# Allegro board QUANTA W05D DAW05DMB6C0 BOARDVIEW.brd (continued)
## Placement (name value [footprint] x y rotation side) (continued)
R15  1k_2  [RC0201_S]  221.12 115.07 180 bottom
R16  10k/f_2  [RC0201_S]  222.67 115.04 180 bottom
R17  0_6  [RC0603]  224.71 114.25 0 bottom
R18  2.2k_2  [RC0201_S]  238.5 114.03 0 bottom
R19  2.2k/f_2  [RC0201_S]  234.41 113.06 180 bottom
R20  20k/f_4  [RC0402]  251.1 112.45 0 bottom
R21  4.7k_2  [RC0201_S]  234.41 112.4 0 bottom
R22  20k/f_2  [RC0201_S]  218.81 111.99 90 bottom
R23  20k/f_2  [RC0201_S]  218.05 111.99 90 bottom
R24  10k_2  [RC0201_S]  202.3 111.66 90 bottom
R25  4.7k_2  [RC0201_S]  201.67 111.66 90 bottom
R26  *100k/f_4  [RC0402]  210.28 111.56 180 bottom
R27  47k/f_4  [RC0402]  204.59 111.1 270 bottom
R28  *0_4/s  [SHORT0402]  203.32 111.1 270 bottom
R29  12.1k/f_4  [RC0402]  216.81 111 270 bottom
R30  15k  [RC0402]  233.7 110.7 180 bottom
R31  *0_6  [RC0603]  219.07 109.76 180 bottom
R32  1k_2  [RC0201_S]  197.86 109.71 0 bottom
R33  47k/f_4  [RC0402]  211.96 109.63 0 bottom
R34  1.3k/f_4  [RC0402]  235.45 109.45 90 bottom
R35  10k_2  [RC0201_S]  217.16 109.05 270 bottom
R36  100/f_2  [RC0201_S]  215.89 109.05 90 bottom
R37  10k/f_2  [RC0201_S]  210.23 108.79 90 bottom
R38  4.7k/f_2  [RC0201_S]  214.01 108.69 90 bottom
R39  0_2  [RC0201_S]  213.4 108.69 90 bottom
R40  *0_2  [RC0201_S]  197.35 108.95 0 bottom
R41  *0_6  [RC0603]  260.32 108.56 180 bottom
R42  10k_2  [RC0201_S]  262.17 108.54 180 bottom
R43  200k_4  [RC0402]  257.19 108.51 180 bottom
R44  10k_2  [RC0201_S]  255.77 108.51 270 bottom
R45  *4.7k_2  [RC0201_S]  216.07 108.21 0 bottom
R46  4.7k_2  [RC0201_S]  197.35 108.18 0 bottom
R47  2.2k_2  [RC0201_S]  236.29 107.24 270 bottom
R48  4.7k_2  [RC0201_S]  263.36 107.19 180 bottom
R49  *0_2/s  [SHORT0201]  197.22 107.29 180 bottom
R50  10k/f_2  [RC0201_S]  197.48 106.41 0 bottom
R51  *0_8  [RC0805]  253.66 106.15 0 bottom
R52  0_2  [RC0201_S]  263.36 106.1 180 bottom
R53  4.7k_2  [RC0201_S]  197.48 105.64 0 bottom
R54  *0_2  [RC0201_S]  263.36 105.24 0 bottom
R55  130/f_4  [RC0402]  61.84 104.78 90 bottom
R56  10k/f_2  [RC0201_S]  252.26 104.63 0 bottom
R57  10k_2  [RC0201_S]  263.36 104.22 180 bottom
R58  *10k/f_2  [RC0201_S]  252.26 103.92 180 bottom
R59  0_6  [RC0603]  253.89 103.74 90 bottom
R60  10k/f_2  [RC0201_S]  251.07 103.74 0 bottom
R61  16.5k/f_4  [RC0402]  122.29 103.74 0 bottom
R62  3.3k/f_4  [RC0402]  124.33 103.48 0 bottom
R63  0_2  [RC0201_S]  196.08 103.1 270 bottom
R64  0_2  [RC0201_S]  195.06 103.1 270 bottom
R65  10k/f_2  [RC0201_S]  252.6 102.9 180 bottom
R66  *10k/f_2  [RC0201_S]  251.07 102.9 0 bottom
R67  *0_2  [RC0201_S]  259.71 102.47 180 bottom
R68  *0_4  [RC0402]  17.92 104.42 270 bottom
R69  0_4  [RC0402]  81.02 64.24 270 bottom
R70  *0_2  [RC0201_S]  259.71 101.71 0 bottom
R71  100k_4 ntc  [RC0402]  16.6 104.42 90 bottom
R72  100k_4 ntc  [RC0402]  81.02 60.94 270 bottom
R73  *100k/f_2  [RC0201_S]  260.19 100.44 0 bottom
R74  *0_6/s  [SHORT0603]  51.38 99.98 270 bottom
R75  *0_6/s  [SHORT0603]  43.43 99.93 270 bottom
R76  10k/f_2  [RC0201_S]  242.82 99.14 270 bottom
R77  *10k/f_2  [RC0201_S]  242.16 99.14 90 bottom
R78  10k/f_2  [RC0201_S]  240.73 99.04 270 bottom
R79  *10k/f_2  [RC0201_S]  240.07 99.04 90 bottom
R80  *10k/f_2  [RC0201_S]  239.01 99.04 270 bottom
R81  *100k_2  [RC0201_S]  75.07 98.71 270 bottom
R82  *10k/f_2  [RC0201_S]  74.41 98.71 270 bottom
R83  43_4  [RC0402]  198.62 98.61 90 bottom
R84  10k/f_2  [RC0201_S]  201.67 98.56 180 bottom
R85  *100k_2  [RC0201_S]  75.71 98.46 270 bottom
R86  10k/f_2  [RC0201_S]  239.84 98.15 180 bottom
R87  15/f_2  [RC0201_S]  88.66 98.13 180 bottom
R88  10k/f_2  [RC0201_S]  242.18 98.02 270 bottom
R89  *10k/f_2  [RC0201_S]  241.42 98.02 270 bottom
R90  100k_2  [RC0201_S]  69.72 98.01 270 bottom
R91  100k/f_2  [RC0201_S]  15.33 97.82 270 bottom
R92  *10k/f_2  [RC0201_S]  201.67 97.8 180 bottom
R93  *0_4/s  [SHORT0402]  73.53 97.64 180 bottom
R94  *0_4/s  [SHORT0402]  71.37 97.64 180 bottom
R95  *0_2  [RC0201_S]  252.21 97.62 180 bottom
R96  150/f_4  [RC0402]  21.46 97.52 0 bottom
R97  *10k_2  [RC0201_S]  23.87 97.26 0 bottom
R98  *0_2  [RC0201_S]  252.21 96.98 0 bottom
R99  *0_2  [RC0201_S]  245.1 96.75 180 bottom
R100  100k_2  [RC0201_S]  195.24 96.6 180 bottom
R101  *6.2k/f_4  [RC0402]  243.32 96.53 0 bottom
R102  10k_2  [RC0201_S]  193.62 96.45 90 bottom
R103  10k_2  [RC0201_S]  192.91 96.45 90 bottom
R104  10k_2  [RC0201_S]  194.4 96.37 90 bottom
R105  *0_2  [RC0201_S]  252.21 96.35 0 bottom
R106  *0_2  [RC0201_S]  245.1 95.99 180 bottom
R107  4.7k_2  [RC0201_S]  223.08 95.86 0 bottom
R108  *10_4  [RC0402]  199.59 95.84 90 bottom
R109  *0_2  [RC0201_S]  252.21 95.71 180 bottom
R110  *0_4  [RC0402]  263.06 95.36 270 bottom
R111  *0_2  [RC0201_S]  245.1 95.23 0 bottom
R112  3.3k/f_2  [RC0402]  76.55 95.2 270 bottom
R113  10k_2  [RC0201_S]  95.12 95.13 180 bottom
R114  10k_2  [RC0201_S]  20.57 95.1 180 bottom
R115  *0_2  [RC0201_S]  252.21 95.08 180 bottom
R116  4.7k_2  [RC0201_S]  201.62 95 180 bottom
R117  *121/f_4  [RC0402]  254.63 94.98 180 bottom
R118  *0_8  [RC0805]  23.36 94.98 90 bottom
R119  *0_2  [RC0201_S]  252.21 94.44 0 bottom
R120  10k/f_2  [RC0201_S]  260.98 94.21 180 bottom
R121  *0_4/s  [SHORT0402]  20.82 94.21 180 bottom
R122  *4.99k/f_2  [RC0201_S]  237.23 93.99 0 bottom
R123  *0_2  [RC0201_S]  236.21 93.99 180 bottom
R124  *0_2  [RC0201_S]  262.12 93.96 180 bottom
R125  4.7k_2  [RC0201_S]  223.08 93.96 0 bottom
R126  *0_2  [RC0201_S]  245.79 93.93 90 bottom
R127  100k/f_2  [RC0201_S]  14.57 93.88 90 bottom
R128  1k_2  [RC0201_S]  13.94 93.88 90 bottom
R129  1k/f_2  [RC0201_S]  13.28 93.88 90 bottom
R130  *4.99k/f_2  [RC0201_S]  226.84 93.81 180 bottom
R131  15/f_2  [RC0201_S]  76.57 93.81 0 bottom
R132  4.7k_2  [RC0201_S]  224.63 93.32 0 bottom
R133  *4.99k/f_2  [RC0201_S]  237.23 93.22 0 bottom
R134  *4.99k/f_2  [RC0201_S]  236.21 93.22 0 bottom
R135  0_2  [RC0201_S]  259.55 93.2 90 bottom
R136  0_2  [RC0201_S]  258.79 93.2 90 bottom
R137  *0_2  [RC0201_S]  228.47 93.15 180 bottom
R138  *4.99k/f_2  [RC0201_S]  226.84 93.15 180 bottom
R139  *10k/f_2  [RC0201_S]  246.52 92.82 270 bottom
R140  *0_6/s  [SHORT0603]  82.08 92.72 180 bottom
R141  15/f_2  [RC0201_S]  87.62 92.56 270 bottom
R142  *0_4  [RC0402]  201.57 92.54 90 bottom
R143  0_4  [RC0402]  12.92 92.51 180 bottom
R144  15/f_2  [RC0201_S]  197.2 92.44 90 bottom
R145  15/f_2  [RC0201_S]  196.33 92.44 90 bottom
R146  *4.99k/f_2  [RC0201_S]  228.47 92.41 180 bottom
R147  *4.99k/f_2  [RC0201_S]  226.84 92.41 180 bottom
R148  *1k_2  [RC0201_S]  64.41 92.41 180 bottom
R149  *4.99k/f_2  [RC0201_S]  237.23 92.33 0 bottom
R150  *4.99k/f_2  [RC0201_S]  236.21 92.33 0 bottom
R151  4.7k_2  [RC0201_S]  224.63 92.33 0 bottom
R152  0_2  [RC0201_S]  262.5 92.31 270 bottom
R153  3.3k/f_2  [RC0402]  86.53 92.28 90 bottom
R154  1m_2  [RC0201_S]  48.79 92.18 0 bottom
R155  *0_6/s  [SHORT0603]  61 92.03 90 bottom
R156  *121/f_4  [RC0402]  256.41 91.8 180 bottom
R157  *121/f_4  [RC0402]  254.37 91.8 180 bottom
R158  *121/f_4  [RC0402]  251.96 91.8 180 bottom
R159  15/f_2  [RC0201_S]  76.19 91.8 0 bottom
R160  *1k_2  [RC0201_S]  64.41 91.78 180 bottom
R161  *4.7k/f_2  [RC0201_S]  224.63 91.7 0 bottom
R162  10k/f_2  [RC0201_S]  223.08 91.7 0 bottom
R163  *4.99k/f_2  [RC0201_S]  226.84 91.55 180 bottom
R164  *0_4/s  [SHORT0402]  46.73 91.55 270 bottom
R165  *4.99k/f_2  [RC0201_S]  237.23 91.52 0 bottom
R166  *0_2  [RC0201_S]  236.21 91.52 0 bottom
R167  *4.99k/f_2  [RC0201_S]  228.47 91.52 0 bottom
R168  *0_4  [RC0402]  39.36 91.47 270 bottom
R169  3.01k/f_2  [RC0201_S]  62.1 91.42 0 bottom
R170  10k/f_2  [RC0201_S]  43.17 91.17 270 bottom
R171  10k_2  [RC0201_S]  42.54 91.17 270 bottom
R172  8.2k/f_4  [RC0402]  55.59 91.12 0 bottom
R173  15/f_2  [RC0201_S]  76.7 91.04 0 bottom
R174  3.01k/f_2  [RC0201_S]  48 91.04 270 bottom
R175  10k_2  [RC0201_S]  20.44 91.04 180 bottom
R176  10k/f_2  [RC0201_S]  224.63 90.86 180 bottom
R177  10k_2  [RC0201_S]  63.44 90.81 180 bottom
R178  4.7k_2  [RC0201_S]  223.08 90.78 0 bottom
R179  *0_6  [RC0603]  82.54 90.78 270 bottom
R180  3.01k/f_2  [RC0201_S]  50.77 90.78 0 bottom
R181  24.9/f_2  [RC0201_S]  49.65 90.78 180 bottom
R182  *4.99k/f_2  [RC0201_S]  228.47 90.56 0 bottom
R183  *4.99k/f_2  [RC0201_S]  226.84 90.56 0 bottom
R184  2.2k_2  [RC0201_S]  195.32 90.4 90 bottom
R185  2.2k_2  [RC0201_S]  194.68 90.4 90 bottom
R186  4.7k_2  [RC0201_S]  223.08 90.12 0 bottom
R187  *0_4  [RC0402]  69.13 89.77 180 bottom
R188  10k_2  [RC0201_S]  79.6 89.69 270 bottom
R189  10k_2  [RC0201_S]  78.96 89.69 270 bottom
R190  10k_2  [RC0201_S]  78.33 89.69 270 bottom
R191  10k_2  [RC0201_S]  77.69 89.69 270 bottom
R192  *4.99k/f_2  [RC0201_S]  226.84 89.64 180 bottom
R193  *4.7k_2  [RC0201_S]  100.7 89.64 90 bottom
R194  *4.7k_2  [RC0201_S]  100.07 89.64 270 bottom
R195  *0_2  [RC0201_S]  99.43 89.64 270 bottom
R196  0_4  [RC0402]  17.01 89.64 0 bottom
R197  1m_4  [RC0402]  189.22 89.51 0 bottom
R198  10k_2  [RC0201_S]  76.95 89.51 270 bottom
R199  10k_2  [RC0201_S]  76.32 89.51 270 bottom
R200  10k/f_2  [RC0201_S]  20.06 89.51 0 bottom
R201  *10k_2  [RC0201_S]  199.31 89.26 180 bottom
R202  10k_2  [RC0201_S]  71.7 88.93 270 bottom
R203  10k_2  [RC0201_S]  71.09 88.91 270 bottom
R204  10k_2  [RC0201_S]  70.48 88.91 270 bottom
R205  *0_4/s  [SHORT0402]  69.08 88.75 0 bottom
R206  *0_4/s  [SHORT0402]  219.45 88.63 180 bottom
R207  *0_4  [RC0402]  217.16 88.65 0 bottom
R208  10k_2  [RC0201_S]  72.33 88.6 270 bottom
R209  *4.7k/f_2  [RC0201_S]  188.66 88.58 180 bottom
R210  15/f_2  [RC0201_S]  231.31 88.55 180 bottom
R211  0_4  [RC0402]  196.21 88.5 90 bottom
R212  *0_4  [RC0402]  195.19 88.5 90 bottom
R213  *0_4/s  [SHORT0402]  20.06 88.5 180 bottom
R214  10k_2  [RC0201_S]  72.99 88.17 270 bottom
R215  10k_2  [RC0201_S]  76.07 88.12 0 bottom
R216  10k_2  [RC0201_S]  75.18 88.12 270 bottom
R217  10k_2  [RC0201_S]  74.54 88.12 270 bottom
R218  10k_2  [RC0201_S]  66.74 88.12 270 bottom
R219  10k_2  [RC0201_S]  66.11 88.12 270 bottom
R220  100k_2  [RC0201_S]  191.64 87.86 90 bottom
R221  100k/f_2  [RC0201_S]  229.76 87.69 180 bottom
R222  4.7k_2  [RC0201_S]  214.47 87.61 270 bottom
R223  4.7k_2  [RC0201_S]  220.57 90.66 270 bottom
R224  4.7k_2  [RC0201_S]  213.12 87.61 270 bottom
R225  4.7k_2  [RC0201_S]  212.49 87.61 270 bottom
R226  4.7k_2  [RC0201_S]  206.34 87.61 0 bottom
R227  *100k_4  [RC0402]  204.46 87.61 90 bottom
R228  *0_4  [RC0402]  202.43 87.48 270 bottom
R229  15/f_2  [RC0201_S]  232.68 87.31 0 bottom
R230  *0_4/s  [SHORT0402]  77.08 87.23 0 bottom
R231  3.3/f_4  [RC0402]  220.21 86.97 270 bottom
R232  3.3/f_4  [RC0402]  219.07 86.97 270 bottom
R233  3.3/f_4  [RC0402]  217.8 86.97 270 bottom
R234  3.3/f_4  [RC0402]  216.65 86.97 270 bottom
R235  *0_4  [RC0402]  91.81 86.95 180 bottom
R236  *0_2/s  [SHORT0201]  199.64 87.1 90 bottom
R237  10k/f_2  [RC0201_S]  224.4 86.85 90 bottom
R238  15/f_2  [RC0201_S]  82.19 87.46 90 bottom
R239  *0_2  [CC0201_S]  71.8 86.82 0 bottom
R240  1k_2  [RC0201_S]  15.74 86.75 90 bottom
R241  *0_4  [RC0402]  93.51 86.44 90 bottom
R242  10k_2  [RC0201_S]  77.41 86.31 0 bottom
R243  100/f_2  [RC0201_S]  20.06 86.06 0 bottom
R244  *51_2  [RC0201_S]  17.65 85.96 180 bottom
R245  *10k_2  [RC0201_S]  224.12 85.93 0 bottom
R246  0_8/fm  [RC0603]  222.17 85.83 0 bottom
R247  *0_4/s  [SHORT0402]  74.29 85.7 270 bottom
R248  1k_2  [RC0201_S]  14.65 85.48 180 bottom
R249  1k/f_2  [RC0201_S]  13.58 85.48 0 bottom
R250  100k/f_2  [RC0201_S]  12.51 85.48 0 bottom
R251  100/f_2  [RC0201_S]  20.06 85.43 0 bottom
R252  10k_4  [RC0402]  213.99 85.32 0 bottom
R253  *51_2  [RC0201_S]  17.65 85.2 180 bottom
R254  100k_2  [RC0201_S]  75.3 85.04 270 bottom
R255  *100k_2  [RC0201_S]  72.38 85.07 270 bottom
R256  *0_4/s  [SHORT0402]  11.17 85.07 90 bottom
R257  2.2k_2  [RC0201_S]  180.89 84.38 180 bottom
R258  51_2  [RC0201_S]  17.65 84.43 180 bottom
R259  0_6  [RC0603]  232.88 82.68 0 bottom
R260  *2.2k_2  [RC0201_S]  227.96 83.8 0 bottom
R261  56.2/f_2  [RC0201_S]  20.03 83.27 180 bottom
R262  100k/f_2  [RC0201_S]  11.57 83.16 270 bottom
R263  100/f_4  [RC0402]  221.99 83.04 0 bottom
R264  2.2k_2  [RC0201_S]  80.87 82.91 270 bottom
R265  *0_4/s  [SHORT0402]  20.06 82.4 180 bottom
R266  62_4  [RC0402]  18.46 82.3 90 bottom
R267  0_2  [RC0201_S]  222.12 82.15 180 bottom
R268  2.2k_2  [RC0201_S]  80.87 81.34 90 bottom
R269  *0_6  [RC0603]  11.3 81.29 90 bottom
R270  51_2  [RC0201_S]  14.72 81.13 180 bottom
R271  *0_6  [RC0603]  73.27 80.75 0 bottom
R272  0_2  [CC0201_S]  70.27 80.57 0 bottom
R273  10k_2  [RC0201_S]  68.7 80.57 180 bottom
R274  *0_2  [RC0201_S]  66.06 80.57 90 bottom
R275  0_2  [RC0201_S]  221.61 80.5 180 bottom
R276  43_4  [RC0402]  20.06 80.24 0 bottom
R277  75/f_4  [RC0402]  17.9 80.24 180 bottom
R278  0_2  [CC0201_S]  15.92 80.17 0 bottom
R279  30.1_4  [RC0402]  201.67 79.99 180 bottom
R280  *0_2  [RC0201_S]  104.13 79.99 90 bottom
R281  *0_2  [RC0201_S]  102.23 79.99 90 bottom
R282  *0_2  [RC0201_S]  99.43 79.99 90 bottom
R283  *0_2  [RC0201_S]  98.8 79.99 90 bottom
R284  *0_2  [RC0201_S]  96.89 79.99 90 bottom
R285  10k_2  [RC0201_S]  68.7 79.96 180 bottom
R286  *4.7k/f_4  [RC0402]  95.24 79.86 180 bottom
R287  10k_2  [RC0201_S]  67.68 79.86 0 bottom
R288  10k_2  [RC0201_S]  66.11 79.76 180 bottom
R289  33_2  [RC0201_S]  221.73 79.23 0 bottom
R290  8.2k/f_4  [RC0402]  69.84 79.23 270 bottom
R291  10k_2  [RC0201_S]  68.7 79.2 180 bottom
R292  *0_2  [RC0201_S]  201.29 79.1 180 bottom
R293  10k_2  [RC0201_S]  67.68 79.1 0 bottom
R294  10k_2  [RC0201_S]  66.11 79 180 bottom
R295  *0_2  [CC0201_S]  15.11 78.95 180 bottom
R296  *0_2  [RC0201_S]  201.29 78.47 180 bottom
R297  *33_4  [RC0402]  101.34 78.47 0 bottom
R298  *22_4  [RC0402]  99.31 78.47 180 bottom
R299  4.7k_2  [RC0201_S]  79.24 78.47 270 bottom
R300  2.2k_2  [RC0201_S]  76.17 78.39 270 bottom
R301  0_2  [CC0201_S]  15.11 78.31 180 bottom
R302  10k_2  [RC0201_S]  67.63 78.21 180 bottom
R303  *10k_2  [RC0201_S]  68.57 77.45 270 bottom
R304  10k_2  [RC0201_S]  66.11 78.21 180 bottom
R305  *1k_2  [RC0201_S]  69.21 77.45 90 bottom
R306  49.9/f_4  [RC0402]  20.82 77.45 90 bottom
R307  1k_2  [RC0201_S]  12.95 77.45 90 bottom
R308  1k_2  [RC0201_S]  12.31 77.45 270 bottom
R309  *0_4/s  [SHORT0402]  70.6 77.07 180 bottom
R310  *0_2  [RC0201_S]  225.42 77.07 90 bottom
R311  *0_4/s  [SHORT0402]  72.76 76.94 0 bottom
R312  4.7k_2  [RC0201_S]  79.24 76.92 90 bottom
R313  10k_2  [RC0201_S]  66.11 76.84 180 bottom
R314  10k_2  [RC0201_S]  67.63 76.81 0 bottom
R315  2.2k_2  [RC0201_S]  76.17 76.59 90 bottom
R316  30.1_4  [RC0402]  201.67 76.43 180 bottom
R317  10k_2  [RC0201_S]  220.46 76.18 180 bottom
R318  *2k/f_4  [RC0402]  206.49 76.05 180 bottom
R319  *2k/f_4  [RC0402]  204.46 76.05 0 bottom
R320  10k_2  [RC0201_S]  70.58 76.05 0 bottom
R321  *10k_2  [RC0201_S]  67.99 75.98 180 bottom
R322  2.2k_2  [RC0201_S]  215.77 75.93 90 bottom
R323  *1k_2  [RC0201_S]  20.19 75.93 0 bottom
R324  100k_2  [RC0201_S]  69.13 75.7 180 bottom
R325  10k_2  [RC0201_S]  71.9 75.39 180 bottom
R326  *1k_2  [RC0201_S]  13.02 75.32 270 bottom
R327  39.2k/f_4  [RC0402]  218.03 75.29 90 bottom
R328  0_8  [RC0805]  17.44 75.21 180 bottom
R329  51_2  [RC0201_S]  20.19 75.16 180 bottom
R330  *0_2  [RC0201_S]  203.4 75.14 180 bottom
R331  *0_2/s  [SHORT0201]  205.48 74.78 270 bottom
R332  *0_2/s  [SHORT0201]  204.46 74.78 270 bottom
R333  10k_2  [RC0201_S]  66.08 74.91 180 bottom
R334  2.49k/f_4  [RC0402]  210.81 75.16 270 bottom
R335  4.7k_4  [RC0402]  207.1 74.68 180 bottom
R336  *10k_2  [RC0201_S]  70.76 74.66 180 bottom
R337  10k_2  [RC0201_S]  69.18 74.55 0 bottom
R338  10k_2  [RC0201_S]  67.58 74.55 180 bottom
R339  100k/f_2  [RC0201_S]  220.46 74.53 0 bottom
R340  10k_2  [RC0201_S]  219.32 74.53 0 bottom
R341  0_2  [RC0201_S]  213.99 74.53 180 bottom
R342  0_2  [CC0201_S]  12.79 74.45 180 bottom
R343  51_2  [RC0201_S]  20.19 74.4 180 bottom
R344  1k_2  [RC0201_S]  14.19 74.22 90 bottom
R345  10k_2  [RC0201_S]  68.34 73.72 0 bottom
R346  *1k_2  [RC0201_S]  66.77 73.72 180 bottom
R347  51_2  [RC0201_S]  19.65 73.72 180 bottom
R348  10k_2  [RC0201_S]  72.05 73.69 0 bottom
R349  1k_2  [RC0201_S]  70.53 73.69 0 bottom
R350  *0_4  [RC0402]  18.03 73.59 0 bottom
R351  *51_2  [RC0201_S]  19.45 72.9 90 bottom
R352  *10k_2  [RC0201_S]  67.63 72.88 180 bottom
R353  10k_2  [RC0201_S]  66.11 72.88 180 bottom
R354  1k_2  [RC0201_S]  15.05 72.75 0 bottom
R355  *0_6  [RC0603]  12.92 72.52 180 bottom
R356  10k_2  [RC0201_S]  73.27 72.5 270 bottom
R357  *1k_2  [RC0201_S]  72.64 72.5 270 bottom
R358  *10k_2  [RC0201_S]  67.63 72.24 180 bottom
R359  10k_2  [RC0201_S]  66.11 72.24 180 bottom
R360  1k_2  [RC0201_S]  70.22 72.09 180 bottom
R361  *51_2  [RC0201_S]  20.26 72.04 0 bottom
R362  *51_2  [RC0201_S]  21.07 71.94 270 bottom
R363  10k_2  [RC0201_S]  67.63 71.2 0 bottom
R364  10k_2  [RC0201_S]  66.11 71.2 180 bottom
R365  *0_4  [RC0201_S]  73.02 70.72 0 bottom
R366  1k_2  [RC0201_S]  14.19 70.39 90 bottom
R367  1.8k/f_4  [RC0402]  12.77 70.39 0 bottom
R368  10k_2  [RC0201_S]  73.02 70.08 180 bottom
R369  2.2k_2  [RC0201_S]  67.66 70.08 180 bottom
R370  1k_2  [RC0201_S]  66.13 70.06 0 bottom
R371  0_4  [RC0402]  70.86 69.91 0 bottom
R372  10k_2  [RC0201_S]  69.33 69.58 0 bottom
R373  10k_2  [RC0201_S]  67.66 68.89 0 bottom
R374  10k_2  [RC0201_S]  66.13 68.86 180 bottom
R375  0_4  [RC0402]  75.18 68.81 0 bottom
R376  2/f_6  [RC0603]  13.81 68.38 270 bottom
R377  10k_2  [RC0201_S]  67.63 67.82 0 bottom
R378  2.2k_2  [RC0201_S]  66.11 67.82 0 bottom
R379  10k_2  [RC0201_S]  73.35 67.8 0 bottom
R380  22.6/f_4  [RC0402]  75.18 67.67 180 bottom
R381  10k_2  [RC0201_S]  71.77 67.62 180 bottom
R382  *0_4/s  [SHORT0402]  66.67 66.91 0 bottom
R383  100k_2  [RC0201_S]  71.75 66.45 0 bottom
R384  1.8k/f_4  [RC0402]  12.59 66.43 180 bottom
R385  *10k_2  [RC0201_S]  71.75 65.82 180 bottom
R386  10m_4  [RC0402]  67.91 65.31 90 bottom
R387  *0_6/s  [SHORT0603]  12.9 65.21 0 bottom
R388  0_4  [RC0402]  71.44 64.9 0 bottom
R389  *10k_2  [RC0201_S]  66.03 64.75 90 bottom
R390  *0_4  [RC0402]  74.54 64.62 180 bottom
R391  *0_4/s  [SHORT0402]  73.02 63.99 270 bottom
R392  100k_2  [RC0201_S]  76.95 64.22 0 bottom
R393  121/f_4  [RC0402]  20.44 63.86 0 bottom
R394  200/f_4  [RC0402]  18.41 63.86 0 bottom
R395  24.9/f_4  [RC0402]  16.27 63.86 180 bottom
R396  10k_2  [RC0201_S]  71.39 63.66 0 bottom
R397  0_4  [RC0402]  74.54 63.61 0 bottom
R398  0_4  [RC0402]  76.83 62.97 180 bottom
R399  10k_2  [RC0201_S]  70.93 62.84 90 bottom
R400  *10k_2  [RC0201_S]  70.3 62.84 270 bottom
R401  *0_4  [RC0402]  74.54 62.59 180 bottom
R402  10k_2  [RC0201_S]  70.86 61.98 0 bottom
R403  10k_2  [RC0201_S]  62.81 61.88 180 bottom
R404  10k_2  [RC0201_S]  61.82 61.88 180 bottom
R405  10k_2  [RC0201_S]  69.33 61.78 180 bottom
R406  10k_2  [RC0201_S]  65.65 61.78 90 bottom
R407  10k_2  [RC0201_S]  64.81 61.78 90 bottom
R408  10k_2  [RC0201_S]  68.14 61.73 90 bottom
R409  10k_2  [RC0201_S]  60.6 61.7 90 bottom
R410  1m_2  [RC0201_S]  59.94 61.7 270 bottom
R411  33_2  [RC0201_S]  56.76 61.7 180 bottom
R412  *1k_2  [RC0201_S]  55.87 61.7 90 bottom
R413  *10k_2  [RC0201_S]  67.45 61.55 90 bottom
R414  10k_2  [RC0201_S]  66.84 61.55 270 bottom
R415  330k_4  [RC0402]  73.63 61.47 180 bottom
R416  0_2  [CC0201_S]  3.29 61.3 0 bottom
R417  100/f_2  [RC0201_S]  21.96 61.19 0 bottom
R418  33_2  [RC0201_S]  58.16 60.81 270 bottom
R419  33_2  [RC0201_S]  57.52 60.81 270 bottom
R420  1k_2  [RC0201_S]  56.76 60.81 270 bottom
R421  33_2  [RC0201_S]  55.87 60.69 270 bottom
R422  10k_2  [RC0201_S]  62.7 60.61 0 bottom
R423  330k_4  [RC0402]  73.63 60.46 0 bottom
R424  0_2  [CC0201_S]  3.32 60.46 0 bottom
R425  10k_2  [RC0201_S]  65.65 60.25 90 bottom
R426  10k_2  [RC0201_S]  64.81 60.25 270 bottom
R427  0_2  [CC0201_S]  3.32 59.82 180 bottom
R428  10k_2  [RC0201_S]  65.65 59.24 90 bottom
R429  *0_2  [CC0201_S]  3.32 59.03 180 bottom
R430  *0_4  [RC0402]  73.42 58.93 90 bottom
R431  0_4  [RC0402]  75.05 58.91 90 bottom
R432  10k/f_2  [RC0201_S]  60.06 58.86 0 bottom
R433  0_2  [CC0201_S]  3.32 58.3 180 bottom
R434  10k/f_2  [RC0201_S]  60.06 58.22 0 bottom
R435  10k_2  [RC0201_S]  60.06 57.59 180 bottom
R436  *0_2  [CC0201_S]  3.32 57.59 0 bottom
R437  *51_2  [RC0201_S]  3.32 56.95 0 bottom
R438  *10k_2  [RC0201_S]  60.06 56.9 0 bottom
R439  49.9/f_4  [RC0402]  73.02 56.88 270 bottom
R440  49.9/f_4  [RC0402]  72 56.88 270 bottom
R441  0_2  [CC0201_S]  76.32 56.83 180 bottom
R442  0_2  [CC0201_S]  75.3 56.49 270 bottom
R443  0_2  [CC0201_S]  74.54 56.49 90 bottom
R444  *0_2  [CC0201_S]  73.91 56.49 90 bottom
R445  *0_4  [RC0402]  76.45 55.22 270 bottom
R446  0_2  [CC0201_S]  67.43 54.97 270 bottom
R447  0_2  [CC0201_S]  67.43 53.95 270 bottom
R448  0_4  [RC0402]  76.45 53.19 90 bottom
R449  0_2  [CC0201_S]  67.43 52.94 270 bottom
R450  0_2  [CC0201_S]  67.43 51.92 270 bottom
R451  *10k/f_2  [RC0201_S]  76.45 51.8 180 bottom
R452  0_2  [CC0201_S]  67.43 50.91 270 bottom
R453  22_4  [RC0402]  77.11 44.1 180 bottom
R454  22_4  [RC0402]  77.11 43.08 180 bottom
R455  470_4  [RC0402]  79.62 42.02 180 bottom
R456  *0_4/s  [SHORT0402]  77.08 41.89 0 bottom
R457  10k/f_2  [RC0201_S]  67.45 39.91 270 bottom
R458  10k/f_2  [RC0201_S]  65.78 39.91 270 bottom
R459  66.5/f_4  [RC0402]  43.81 27.06 180 bottom
R460  66.5/f_4  [RC0402]  41.78 27.06 0 bottom
R461  1.8k/f_4  [RC0402]  47.19 26.9 180 bottom
R462  10k/f_4  [RC0402]  67.56 26.4 270 bottom
R463  *0_4  [RC0402]  56 26.4 90 bottom
R464  220k_4  [RC0402]  54.86 26.4 270 bottom
R465  *2m/f_4  [RC0402]  53.71 26.4 90 bottom
R466  1.8k/f_4  [RC0402]  43.17 25.38 90 bottom
R467  2/f_6  [RC0603]  42 25.1 270 bottom
R468  *0_6  [RC0603]  40.76 25.1 270 bottom
R469  4.7k_2  [RC0201_S]  72.89 24.49 0 bottom
R470  24.9/f_4  [RC0402]  41.55 23.14 180 bottom
R471  100k_2  [RC0201_S]  68.19 20.55 180 bottom
R472  *0_4  [RC0402]  24.12 13.82 90 bottom
R473  *0_2  [RC0201_S]  12.87 13.67 270 bottom
R474  *0_2  [RC0201_S]  12.23 13.67 270 bottom
R475  *0_8  [RC0805]  9.72 13.47 270 bottom
R476  *0_8  [RC0805]  7.36 13.47 270 bottom
R477  4.7k_2  [RC0201_S]  184.17 80.85 270 bottom
R478  *0_6  [RC0603]  232.88 83.83 0 bottom
R479  *4.7k_2  [RC0201_S]  200.65 97.13 180 bottom
R480  4.7k_2  [RC0201_S]  212.46 108.44 0 bottom
R481  *0_2  [RC0201_S]  247.55 91.67 90 top
R482  *4.7k_2  [RC0201_S]  79.57 84.54 180 bottom
R483  0_2  [RC0201_S]  231.18 84.18 270 bottom
R484  *0_2  [RC0201_S]  230.29 88.91 180 bottom
R485  *4.7k_2  [RC0201_S]  79.57 85.55 180 bottom
R486  *0_2  [RC0201_S]  248.21 91.67 90 top
R487  *0_2  [RC0201_S]  249.6 91.8 90 top
R488  *0_2  [RC0201_S]  250.26 91.8 90 top
RP1  10k_10p8r_6  [10P8R]  74.16 94.85 0 bottom
RP2  10k_10p8r_6  [10P8R]  66.67 94.75 0 bottom
RP3  10k_10p8r_6  [10P8R]  70.35 94.72 0 bottom
RP4  *0_4p2r_4  [4P2R-0404]  40.91 91.42 0 bottom
TP1  *  [TP1250-P14_4]  214.7 105.59 0 top
TP2  *  [TP1250-P14_4]  216.32 105.42 0 top
TP3  *  [TP1250-P14_4]  213.73 104.25 0 top
TP4  *  [TP1250-P14_4]  217.04 104.25 0 top
TP5  *  [TP1250-P14_4]  215.21 103.99 0 top
TP6  *  [TP1250-P14_4]  212.21 103.61 0 top
TP7  *  [TP1250-P14_4]  219.83 103.1 0 top
TP8  *  [TP1250-P14_4]  215.79 102.82 0 top
TP9  *  [TP1250-P14_4]  213.94 102.75 0 top
TP10  *  [TP1250-P14_4]  212.18 99.57 0 top
TP11  *  [TP1250-P14_4]  32.22 89.82 0 top
TP12  *  [TP1250-P14_4]  30.73 89.77 0 top
TP13  *  [TP1250-P14_4]  63.06 89.64 0 top
TP14  *  [TP1250-P14_4]  23.61 84.69 0 top
TP15  *  [TP1250-P14_4]  21.84 83.8 0 top
TP16  *  [TP1250-P14_4]  24.43 82.4 0 top
TP17  *  [TP1250-P14_4]  26.41 82.4 0 top
TP18  *  [TP1250-P14_4]  55.41 82.4 0 top
TP19  *  [TP1250-P14_4]  21.96 81.89 0 top
TP20  *  [TP1250-P14_4]  77.59 81.77 0 top
TP21  *  [TP1250-P14_4]  23.36 81.06 0 top
TP22  *  [TP1250-P14_4]  25.52 80.75 0 top
TP23  *  [TP1250-P14_4]  27.04 80.62 0 top
TP24  *  [TP1250-P14_4]  20.54 80.6 0 top
TP25  *  [TP1250-P14_4]  57.78 80.5 0 top
TP26  *  [TP1250-P14_4]  24.27 79.99 0 top
TP27  *  [TP1250-P14_4]  21.71 79.86 0 top
TP28  *  [TP1250-P14_4]  20.06 78.72 0 top
TP29  *  [TP1250-P14_4]  62.6 78.11 0 top
TP30  *  [TP1250-P14_4]  64.51 77.83 0 top
TP31  *  [TP1250-P14_4]  22.04 77.37 0 top
TP32  *  [TP1250-P14_4]  20.95 76.69 0 top
TP33  *  [TP1250-P14_4]  17.9 76.43 0 top
TP34  *  [TP1250-P14_4]  57.65 76.43 0 top
TP35  *  [TP1250-P14_4]  57.27 75.16 0 top
TP36  *  [TP1250-P14_4]  16.88 75.04 0 top
TP37  *  [TP1250-P14_4]  20.95 75.04 0 top
TP39  *  [TP1250-P14_4]  62.37 74.81 0 top
TP40  *  [TP1250-P14_4]  43.81 73.77 0 top
TP41  *  [TP1250-P14_4]  4.18 73.64 0 top
TP42  *  [TP1250-P14_4]  16.93 73.64 0 top
TP43  *  [TP1250-P14_4]  51.94 73.26 0 top
TP44  *  [TP1250-P14_4]  62.6 72.95 0 top
TP45  *  [TP1250-P14_4]  57.42 72.88 0 top
TP46  *  [TP1250-P14_4]  17.65 72.52 0 top
TP47  *  [TP1250-P14_4]  4.18 72.37 0 top
TP48  *  [TP1250-P14_4]  66.21 71.51 0 top
TP49  *  [TP1250-P14_4]  54.98 71.23 0 top
TP50  *  [TP1250-P14_4]  4.18 71.1 0 top
TP51  *  [TP1250-P14_4]  63.21 70.74 0 top
TP52  *  [TP1250-P14_4]  68.06 70.72 0 top
TP53  *  [TP1250-P14_4]  4.18 69.83 0 top
TP54  *  [TP1250-P14_4]  4.18 68.56 0 top
TP55  *  [TP1250-P14_4]  64.97 68.38 0 top
TP56  *  [TP1250-P14_4]  4.18 67.29 0 top
TP57  *  [TP1250-P14_4]  43.55 67.04 0 top
TP58  *  [TP1250-P14_4]  4.18 66.02 0 top
TP59  *  [TP1250-P14_4]  61.05 65.13 0 top
TP60  *  [TP1250-P14_4]  4.18 64.75 0 top
TP61  *  [TP1250-P14_4]  3.17 62.72 0 top
TP62  *  [TP1250-P14_4]  5.33 61.19 0 top
TP63  *  [TP1250-P14_4]  69.59 52.56 0 top
TP64  *  [TP2650]  237.02 113.85 180 bottom
TP65  *  [TP2650]  235.7 113.85 180 bottom
TP66  *  [TP2675]  89.65 99.17 270 bottom
TP67  *  [TP2050]  23.61 97.9 180 bottom
TP68  *  [TP2075]  76.7 96.65 270 bottom
TP69  *  [TP2650]  88.38 94.47 270 bottom
TP70  *  [TP2675]  76.75 92.82 270 bottom
TP71  *  [TP2650]  63.01 92.41 180 bottom
TP72  *  [TP2650]  88.64 92.31 270 bottom
TP73  *  [TP2650]  78.86 92.31 270 bottom
TP74  *  [TP2650]  47.9 92.13 180 bottom
TP75  *  [TP2050]  220.87 92 180 bottom
TP76  *  [TP2650]  50.16 91.45 180 bottom
TP77  *  [TP2050]  213.73 87.91 180 bottom
TP78  *  [TP2650]  19.17 89.64 180 bottom
TP79  *  [TP2650]  16.68 88.68 180 bottom
TP80  *  [TP2650]  18.13 88.63 180 bottom
TP81  *  [TP2650]  15.69 87.86 180 bottom
TP82  *  [TP2650]  19.37 87.1 180 bottom
TP83  *  [TP2650]  16.63 86.85 180 bottom
TP84  *  [TP2650]  18.53 83.8 180 bottom
TP85  *  [TP2650]  21.51 80.07 180 bottom
TP86  *  [TP1250-P14_4]  64.2 79.81 180 bottom
TP87  *  [TP2050]  22.31 79.04 180 bottom
TP88  *  [TP2675]  64.61 77.35 180 bottom
TP89  *  [TP2650]  21.07 75.98 180 bottom
TP90  *  [TP2675]  72.74 75.93 180 bottom
TP91  *  [TP1250-P14_4]  14.88 71 180 bottom
TP92  *  [TP2650]  68.57 68.94 180 bottom
TP93  *  [TP2650]  72.89 68.81 180 bottom
TP94  *  [TP2650]  20.26 64.9 180 bottom
TP95  *  [TP2050]  50.67 60.64 180 bottom
TP96  *  [TP2050]  62.6 61.22 180 bottom
TP97  *  [TP2650]  27.42 61.19 180 bottom
TP98  *  [TP2650]  26.15 61.19 180 bottom
TP99  *  [TP2650]  24.88 61.19 180 bottom
TP100  *  [TP2050]  51.48 59.49 180 bottom
TP101  *  [TP2050]  63.14 59.97 180 bottom
TP102  *  [TP2650]  64.71 59.39 180 bottom
TP103  *  [TP2650]  63.11 58.65 180 bottom
TP104  *  [TP2650]  65.63 58.25 180 bottom
TP105  *  [TP2650]  64.33 58.15 180 bottom
TP106  *  [TP2675]  63.21 56.98 180 bottom
U1  hp303dlhctr  [LGA14-5X3-8]  227.45 117.84 180 top
U3  *sn74cbtlv3126rgyr  [VQFN14-3_5X3_5-5-15P]  6.9 57.36 90 top
U4  g677l308a31u  [ADFN6-1_5X1_5]  207.87 110.93 180 bottom
U5  stm32f103rbt6tr  [LQFP64-12X12-5-STM32F405RGT6TR]  243.45 106.53 180 bottom
U6  *g9191-330t1u  [SOT23-5]  257.12 102.37 270 bottom
U7  kb9010qf c4  [LQFP128-16X16-4]  211.3 98.36 90 bottom
U8  ic(5p) g5243at11u  [SOT23-5]  13.25 97.16 0 bottom
U9  en25q32b-104hip  [SOIC8-8-1_27]  82.54 96.09 270 bottom
U10  *pi3eqx6741stzde  [QFN20-4X4-5-21P-ADG786]  248.79 95.99 0 bottom
U11  *74aup1g07gw  [SOT353-1-2_125-65-5P]  18.28 95.1 0 bottom
U12  *sn65lvpe502a  [PVQFN24-4X4-5-34P]  232.35 92.11 270 bottom
U13  g781-1p8  [MSOP8-4_9-65]  92.35 91.03 0 bottom
U14  tlv70233dbvr  [SOT23-5]  210.69 85.07 0 bottom
U15  *slb9635tt1.2-fw3.17  [TSSOP28-6_4-65]  99.81 84.82 0 bottom
U16  *tc7sh08fu  [SSOP5-P-A-TOSHIBA-B]  76.98 84.13 180 bottom
U17  ic(5p) g5243at11u  [SOT23-5]  73.91 83.04 90 bottom
U18  92hd95 40_qfn  [QFN40-5X5-4-41P-92HD99]  217.42 80.12 270 bottom
U19  hpa00929rtjr  [PWQFN20-4X4-5-30P]  205.61 79.48 90 bottom
U20  hsw_ult_ddr3l  [BGA1168-INTEL-HASWELL]  43.5 76.4 0 bottom
U21  *emc1412-1-aczl-tr  [MSOP8-4_9-65]  78.86 52.94 180 bottom
U22  *74aup1g07gw  [SOT353-1-2_125-65-5P]  60.44 26.4 270 bottom
U23  l3gd20tr  [LGA16-4X4-65]  234.05 117.84 90 top
U*  -  [unnamed#2]  280.54 77.7 0 top
U*#2  -  [unnamed#2]  15.87 107.8 0 top
U*#3  -  [unnamed#2]  3.17 10.39 0 top
U*#4  -  [unnamed#2]  17.26 110.6 180 bottom
U*#5  -  [unnamed#2]  225.16 118.6 180 bottom
U*#6  -  [unnamed#2]  280.15 74.15 180 bottom
Y1  12mhz +20ppm  [XTL-3_2X2_5-2_2X1_8-4P]  253.36 109.2 90 bottom
Y2  24mhz +-30ppm  [XTL-3_2X2_5-2_2X1_7-0_8H]  48.25 95.61 180 bottom
Y3  *32.768khz  [XTL-3_2X1_5-2_5-0_8H]  108.2 84.69 0 bottom
Y4  32.768khz  [XTL-3_2X1_5-2_5-0_8H]  69.38 65.89 270 bottom

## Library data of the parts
C1 C14 C24 C25 C28 C36 C39 C40 C42-C45 C51 C52 C56 C57 C64 C74 C87 C88 C90 C91 C94 C96-C98 C104 C109 C111 C114 C115 C121 C133 C137 C138 C148 C154 C158-C161 C187 C193 C196 C197 C202 C203 C205 C206 C208 C210-C215 C219 C221 C235 C236 C246 C251 C257 C258 C273 C278 C279 C281 C296-C298 C314-C318 C342 C361 C363 EC10 EC13 EC14 PC5-PC7 PC11-PC14 PC17 PC19-PC25 PC27-PC31 PC35-PC44 PC46 PC47 PC50-PC52 PC54 PC55 PC59-PC61 PC64 PC73-PC75 PC77-PC80 PC83 PC85-PC90 PC92 PC94 PC95 PC97 PC98 PC100 PC101 PC103-PC105 PC112-PC114 PC116-PC125 PC129-PC131 PC133-PC140 PC142 PC143 PC148-PC152 = CC0402
C2 C11 C12 C27 C54 C69 C75 C110 C126 C139 C147 C163 C191 C217 C218 C223 C225 C226 C229 C234 C240 C248 C254 C256 C261 C264 C272 C280 C319-C322 C325-C337 C339 C344 C346 C355-C357 C362 PC18 PC26 PC45 PC53 PC68 PC84 PC91 PC96 PC99 PC107 PC115 PC126 PC132 PC141 PC147 = CC0603
C3-C5 C9 C13 C15-C19 C22 C23 C26 C29-C34 C37 C38 C41 C50 C53 C55 C58 C65-C68 C72 C73 C76 C82-C85 C89 C92 C99-C102 C112 C113 C118 C119 C122 C125 C128 C134 C135 C140-C145 C149 C150 C152 C153 C155 C157 C162 C167-C176 C178-C186 C188-C190 C192 C194 C195 C198-C201 C204 C207 C209 C216 C220 C222 C224 C227 C228 C230-C233 C237 C239 C241-C245 C247 C250 C252 C253 C255 C260 C262 C263 C265-C271 C274-C277 C282-C295 C299-C313 C323 C324 C338 C340 C341 C343 C345 C347-C354 C358-C360 C364 C365 EC1-EC9 EC11 EC12 EC15 R239 R272 R278 R295 R301 R342 R416 R424 R427 R429 R433 R436 R441-R444 R446 R447 R449 R450 R452 = CC0201_S
C8 C20 C21 C35 C46-C49 C59-C63 C70 C71 C77-C81 C86 C93 C95 C103 C105-C108 C116 C117 C120 C123 C124 C127 C129-C132 C136 C146 C151 C156 C164-C166 C177 C238 C249 C259 C366 PC8-PC10 PC15 PC16 PC32-PC34 PC48 PC49 PC56 PC57 PC62 PC63 PC65-PC67 PC69-PC72 PC76 PC81 PC82 PC93 PC102 PC108-PC111 PC127 PC128 PC144 PC145 = CC0805
CN1 = BSH-030-01-L-D-A-TR-60P-LDH
CN2 = 88511-180N-18P-L
CN3 = 50208-01001-001-10P-L
CN4 = ML1220-SMT
CN5 CN14 = MINIPCI-MPCET-SSC10-TS10-52P
CN6 = GS12407-11141-9H-40P-R
CN7 = 50406-02071-001-20P-R
CN8 = FH35C-31S-0_3SHW-31P-LDH
CN9 = 51278-00941-001-9P-L
CN10 FAN1 = 50505-00441-001-4P-L
CN11 = 88194-1001-10P-L
CN12 = 50505-00641-V01-6P-L
CN13 = 196090-16021-3-16P-L-SMT
D1 PD2 PQ4 PQ8 PQ9 Q1-Q4 Q6-Q11 Q17 Q18 Q23 Q24 Q26 Q27 = SOT23_213-3_3-2
D2-D10 PD4 PD5 PD7 PD8 = DSM
H1 = H-TE354X299BC91D91P2
H2 = H-TE354X339BC91D91P2
H3 = H-TE354X339BC138D138P2
H4 = H-TE473X378BC138D138P2
H5-H7 H9 = H-TC236IC142BC142D142P2
H8 = H-TE354X366BC138D138P2
H10 = H-TE413X295BC142D142P2
H11 = H-TE315X354BC138D138P2
H14 = H-C91D91N
JDIM1 = DDR-DDRRK-20401-TP4B-204P-RUV
L1 L3 L4 L6-L11 L13-L18 PR1 PR16 PR21 PR29 PR30 PR36 PR38 PR42 PR43 PR50 PR63 PR66 PR69 PR86 PR113 PR125 PR132 R17 R31 R41 R59 R179 R246 R259 R269 R271 R355 R376 R467 R468 R478 = RC0603
L2 L12 = CHOKE-WCM2012-4P
L5 PL1 PL3 PL6 PL8 PL15 R10 R11 = SHORT0805
PC1-PC4 = CC3528
PC58 PC106 PC146 = CC7343-2_15H
PD1 PD3 PD6 = D-DO-214AC
PJP1-PJP4 = SHORT-SOLDERJUMPER-3
PL2 = L3_2X2_5-1_55
PL4 PL5 PL9 PL11 PL14 = CHOKE-MPL73-1R5
PL7 = CHOKE-ETQP4LR36AFM
PL10 PL12 PL13 PR100 PR102 R51 R118 R328 R475 R476 = RC0805
PQ1 PQ2 PQ5 PQ10 PQ11 PQ13-PQ15 = PG-TSDSON-8-8P-R
PQ3 = POWER-5X6-1_27-7P
PQ6 = SO-8FL-5P
PQ7 = TO252_134-9_9-4_57-SMT
PQ12 = SOT363-2_1-65-6P
PR2 PR3 PR6 PR8-PR15 PR18-PR20 PR23 PR24 PR27 PR28 PR31-PR34 PR44 PR47 PR48 PR51 PR53 PR58 PR61 PR62 PR64 PR65 PR67 PR70 PR72 PR75 PR76 PR81-PR84 PR87 PR89-PR94 PR97-PR99 PR104 PR106-PR112 PR114 PR118-PR124 PR127 PR128 R20 R26 R27 R29 R30 R33 R34 R43 R55 R61 R62 R68 R69 R71 R72 R83 R96 R101 R108 R110 R112 R117 R142 R143 R153 R156-R158 R168 R172 R187 R196 R197 R207 R211 R212 R227 R228 R231-R235 R241 R252 R263 R266 R276 R277 R279 R286 R290 R297 R298 R306 R316 R318 R319 R327 R334 R335 R350 R367 R371 R375 R380 R384 R386 R388 R390 R393-R395 R397 R398 R401 R415 R423 R430 R431 R439 R440 R445 R448 R453-R455 R459-R466 R470 R472 = RC0402
PR4 PR5 PR17 PR22 PR25 PR26 PR35 PR37 PR41 PR45 PR46 PR52 PR54-PR57 PR60 PR68 PR71 PR73 PR74 PR77 PR79 PR80 PR95 PR96 PR129-PR131 R1 R6-R9 R28 R93 R94 R121 R164 R205 R206 R213 R230 R247 R256 R265 R309 R311 R382 R391 R456 = SHORT0402
PR7 PR39 PR40 PR59 PR78 PR85 PR88 PR101 PR105 PR115 PR116 PR126 R49 R236 R331 R332 = SHORT0201
PR49 R74 R75 R140 R155 R387 = SHORT0603
PR103 PR117 = F3_2X1_65-2_8
PU1 = QFN23-4X4-5
PU2 = TSOP6-2_8-95
PU3 = QFN28-4X4-4-29P-NCP81101MNTWG
PU4 PU5 = QFN14-3X3-4-16P
PU6 PU8 = TQFN20-3X3-4-21P
PU7 = PVQFN20-3_5X3_5-5-25P
Q5 = D-SOT523_213-1_6-1
Q12 Q13 Q25 = UMT_213-3-1_3
Q14 Q15 = SOT523_213-1_6-1-3P
Q16 Q19-Q22 Q30 = SC70-2_1-65-6P
R2-R5 R12-R16 R18 R19 R21-R25 R32 R35-R40 R42 R44-R48 R50 R52-R54 R56-R58 R60 R63-R67 R70 R73 R76-R82 R84-R92 R95 R97-R100 R102-R107 R109 R111 R113-R116 R119 R120 R122-R139 R141 R144-R152 R154 R159-R163 R165-R167 R169-R171 R173-R178 R180-R186 R188-R195 R198-R204 R208-R210 R214-R226 R229 R237 R238 R240 R242-R245 R248-R251 R253-R255 R257 R258 R260-R262 R264 R267 R268 R270 R273-R275 R280-R285 R287-R289 R291-R294 R296 R299 R300 R302-R305 R307 R308 R310 R312-R315 R317 R320-R326 R329 R330 R333 R336-R341 R343-R349 R351-R354 R356-R366 R368-R370 R372-R374 R377-R379 R381 R383 R385 R389 R392 R396 R399 R400 R402-R414 R417-R422 R425 R426 R428 R432 R434 R435 R437 R438 R451 R457 R458 R469 R471 R473 R474 R477 R479-R488 = RC0201_S
RP1-RP3 = 10P8R
RP4 = 4P2R-0404
TP1-TP37 TP39-TP63 TP86 TP91 = TP1250-P14_4
TP64 TP65 TP69 TP71-TP74 TP76 TP78-TP85 TP89 TP92-TP94 TP97-TP99 TP102-TP105 = TP2650
TP66 TP70 TP88 TP90 TP106 = TP2675
TP67 TP75 TP77 TP87 TP95 TP96 TP100 TP101 = TP2050
TP68 = TP2075
U1 = LGA14-5X3-8
U3 = VQFN14-3_5X3_5-5-15P
U4 = ADFN6-1_5X1_5
U5 = LQFP64-12X12-5-STM32F405RGT6TR
U6 U8 U14 U17 = SOT23-5
U7 = LQFP128-16X16-4
U9 = SOIC8-8-1_27
U10 = QFN20-4X4-5-21P-ADG786
U11 U22 = SOT353-1-2_125-65-5P
U12 = PVQFN24-4X4-5-34P
U13 U21 = MSOP8-4_9-65
U15 = TSSOP28-6_4-65
U16 = SSOP5-P-A-TOSHIBA-B
U18 = QFN40-5X5-4-41P-92HD99
U19 = PWQFN20-4X4-5-30P
U20 = BGA1168-INTEL-HASWELL
U23 = LGA16-4X4-65
Y1 = XTL-3_2X2_5-2_2X1_8-4P
Y2 = XTL-3_2X2_5-2_2X1_7-0_8H
Y3 Y4 = XTL-3_2X1_5-2_5-0_8H

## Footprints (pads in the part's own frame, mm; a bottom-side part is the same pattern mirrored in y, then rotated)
4P2R-0404
  rect 0.33x0.762 smd: 1(-0.325,-0.5) 2(-0.325,0.5) 3(0.325,-0.5) 4(0.325,0.5)
10P8R
  rect 0.305x1.092 smd: 1(-1.27,-0.85) 2(-0.635,-0.85) 3(0,-0.85) 4(0.635,-0.85) 5(1.27,-0.85) 6(1.27,0.85) 7(0.635,0.85) 8(0,0.85) 9(-0.635,0.85) 10(-1.27,0.85)
50208-01001-001-10P-L
  rect 0.508x0.991 smd: 1(-3.6,1.95) 2(-2.8,1.95) 3(-2,1.95) 4(-1.2,1.95) 5(-0.4,1.95) 6(0.4,1.95) 7(1.2,1.95) 8(2,1.95) 9(2.8,1.95) 10(3.6,1.95)
  rect 1.194x1.702 smd: 11(-4.9,0) 12(4.9,0)
50406-02071-001-20P-R
  rect 0.254x1.295 smd: 1(4.75,1.95) 2(4.25,1.95) 3(3.75,1.95) 4(3.25,1.95) 5(2.75,1.95) 6(2.25,1.95) 7(1.75,1.95) 8(1.25,1.95) 9(0.75,1.95) 10(0.25,1.95) 11(-0.25,1.95) 12(-0.75,1.95) 13(-1.25,1.95) 14(-1.75,1.95) 15(-2.25,1.95) 16(-2.75,1.95) 17(-3.25,1.95) 18(-3.75,1.95) 19(-4.25,1.95) 20(-4.75,1.95)
  rect 1.194x2.692 smd: 21(7.15,0) 22(-7.15,0)
  rect 2.311x1.295 smd: 23(3.9,-1.95) 24(-3.9,-1.95)
50505-00441-001-4P-L
  rect 0.61x1.295 smd: 1(-1.5,3.25) 2(-0.5,3.25) 3(0.5,3.25) 4(1.5,3.25)
  rect 0.991x2.007 smd: 5(-4.1,0) 6(4.1,0)
50505-00641-V01-6P-L
  rect 0.61x1.295 smd: 1(-2.5,3.25) 2(-1.5,3.25) 3(-0.5,3.25) 4(0.5,3.25) 5(1.5,3.25) 6(2.5,3.25)
  rect 0.991x2.007 smd: 7(-5.1,0) 8(5.1,0)
51278-00941-001-9P-L
  rect 0.787x1.905 smd: 1(-5,4.925) 2(-3.75,4.925) 3(-2.5,4.925) 4(-1.25,4.925) 5(0,4.925) 6(1.25,4.925) 7(2.5,4.925) 8(3.75,4.925) 9(5,4.925)
  rect 1.295x3.353 smd: 10(-7.85,0) 11(7.85,0)
88194-1001-10P-L
  rect 0.305x0.889 smd: 1(-2.25,3.05) 2(-1.75,3.05) 3(-1.25,3.05) 4(-0.75,3.05) 5(-0.25,3.05) 6(0.25,3.05) 7(0.75,3.05) 8(1.25,3.05) 9(1.75,3.05) 10(2.25,3.05)
  rect 0.991x2.007 smd: 11(-4.35,0) 12(4.35,0)
88511-180N-18P-L
  rect 0.305x1.295 smd: 1(-4.25,2.8) 2(-3.75,2.8) 3(-3.25,2.8) 4(-2.75,2.8) 5(-2.25,2.8) 6(-1.75,2.8) 7(-1.25,2.8) 8(-0.75,2.8) 9(-0.25,2.8) 10(0.25,2.8) 11(0.75,2.8) 12(1.25,2.8) 13(1.75,2.8) 14(2.25,2.8) 15(2.75,2.8) 16(3.25,2.8) 17(3.75,2.8) 18(4.25,2.8)
  rect 1.803x1.397 smd: 19(-5.9,0) 20(5.9,0)
196090-16021-3-16P-L-SMT
  rect 0.508x1.295 smd: 1(-7.5,2.65) 2(-6.5,2.65) 3(-5.5,2.65) 4(-4.5,2.65) 5(-3.5,2.65) 6(-2.5,2.65) 7(-1.5,2.65) 8(-0.5,2.65) 9(0.5,2.65) 10(1.5,2.65) 11(2.5,2.65) 12(3.5,2.65) 13(4.5,2.65) 14(5.5,2.65) 15(6.5,2.65) 16(7.5,2.65)
  rect 1.803x1.397 smd: 17(-9.65,0) 18(9.65,0)
ADFN6-1_5X1_5
  rect 0.787x0.254 smd: 1(0.55,-0.5)
  rect 0.711x0.254 smd: 2(0.6,0) 3(0.6,0.5) 4(-0.6,0.5) 5(-0.6,0) 6(-0.6,-0.5)
BGA1168-INTEL-HASWELL
  round 0.508 smd: A3(18.177,-11.314) A62(-18.722,-11.314) AW1(19.314,10.727) AW63(-19.314,10.743) AY2(18.771,11.314) AY62(-18.748,11.314) B2(18.806,-10.806) B63(-19.314,-10.722) C1(19.314,-10.177)
  round 0.381 smd: A4(17.421,-11.314) A5(16.76,-11.314) A6(15.564,-11.314) A59(-16.586,-11.314) A60(-17.412,-11.314) A61(-18.072,-11.314) AA9(14.282,0.262) AA21(7.627,0.175) AA23(6.199,0.175) AA58(-16.063,0.015) AB10(13.838,0.738) AB20(8.135,0.582) AB21(7.627,0.988) AB22(6.707,0.582) AB23(6.199,0.988) AB57(-15.743,0.666) AC9(14.282,1.215) AC20(8.135,1.394) AC22(6.707,1.394) AC58(-16.063,1.316) AD10(13.838,1.691) AD21(7.627,1.801) AD23(6.199,1.801) AD57(-15.743,1.966) AE9(14.282,2.167) AE10(13.838,2.643) AE20(8.135,2.207) AE21(7.627,2.614) AE22(6.707,2.207) AE23(6.199,2.614) AE58(-16.063,2.616) AF9(14.282,3.12) AF11(13.255,2.968) AF12(12.442,2.968) AF14(11.63,2.968) AF15(10.817,2.968) AF17(10.004,2.968) AF18(9.191,2.968) AF20(8.378,2.968) AF22(6.707,3.02) AG10(13.662,3.476) AG11(12.849,3.476) AG13(12.036,3.476) AG14(11.223,3.476) AG16(10.41,3.476) AG17(9.598,3.476) AG19(8.785,3.476) AG20(7.972,3.476) AG23(6.199,3.426) AG57(-15.743,3.267) AG58(-16.377,3.695) AH22(6.707,3.833) AH24(5.394,3.975) AH26(4.094,3.975) AH28(2.793,3.975) AH30(1.493,3.975) AH32(0.192,3.975) AH34(-1.108,3.975) AH36(-2.409,3.975) AH38(-3.709,3.975) AH40(-5.01,3.975) AH42(-6.31,3.975) AH44(-7.611,3.975) AH46(-8.911,3.975) AH49(-10.212,3.975) AH51(-11.512,3.975) AH53(-12.813,3.975) AH55(-14.113,3.975) AH57(-15.413,3.975) AJ23(6.199,4.239) AJ25(4.744,4.3) AJ27(3.443,4.3) AJ29(2.143,4.3) AJ31(0.843,4.3) AJ33(-0.458,4.3) AJ35(-1.758,4.3) AJ37(-3.059,4.3) AJ39(-4.359,4.3) AJ41(-5.66,4.3) AJ43(-6.96,4.3) AJ45(-8.261,4.3) AJ47(-9.561,4.3) AJ50(-10.862,4.3) AJ52(-12.162,4.3) AJ54(-13.463,4.3) AJ56(-14.763,4.3) AJ58(-16.064,4.3) AT1(19.314,8.683) AT63(-19.314,8.533) AU1(19.314,9.343) AU63(-19.314,9.359) AV1(19.314,10.004) AV2(18.654,9.993) AV62(-18.664,10.004) AV63(-19.314,10.019) AW2(18.654,10.654) AW3(17.993,10.654) AW61(-18.014,10.664) AW62(-18.664,10.664) AY3(18.047,11.314) AY4(17.387,11.314) AY5(16.726,11.314) AY59(-16.774,11.314) AY60(-17.434,11.314) AY61(-18.095,11.314) B3(18.056,-10.664) B61(-18.001,-10.654) B62(-18.664,-10.59) C2(18.664,-10.056) C62(-18.664,-9.93) C63(-19.314,-9.998) D1(19.314,-9.453) D63(-19.314,-9.338) E1(19.314,-8.792) E23(5.981,-8.713) E25(4.6,-8.713) E27(3.474,-8.713) E29(2.093,-8.713) E31(0.966,-8.713) E33(-0.415,-8.713) E35(-1.541,-8.713) E37(-2.922,-8.713) E39(-4.049,-8.713) E41(-5.43,-8.713) E43(-6.556,-8.713) E45(-7.937,-8.713) E47(-9.064,-8.713) E49(-10.444,-8.713) E51(-11.571,-8.713) E53(-12.952,-8.713) E55(-14.079,-8.713) E57(-15.459,-8.713) E63(-19.314,-8.667) F1(19.314,-7.878) F22(6.597,-8.256) F24(5.291,-8.188) F26(4.037,-8.188) F28(2.783,-8.188) F30(1.53,-8.188) F32(0.276,-8.188) F34(-0.978,-8.188) F36(-2.232,-8.188) F38(-3.485,-8.188) F40(-4.739,-8.188) F42(-5.993,-8.188) F44(-7.247,-8.188) F46(-8.5,-8.188) F48(-9.754,-8.188) F50(-11.008,-8.188) F52(-12.262,-8.188) F54(-13.515,-8.188) F56(-14.769,-8.188) F58(-16.063,-8.188) G22(6.707,-7.546) G23(5.981,-7.863) G25(4.6,-7.863) G27(3.474,-7.863) G29(2.093,-7.863) G31(0.966,-7.863) G33(-0.415,-7.863) G35(-1.541,-7.863) G37(-2.922,-7.863) G39(-4.049,-7.863) G41(-5.43,-7.863) G43(-6.556,-7.863) G45(-7.937,-7.863) G47(-9.064,-7.863) G49(-10.444,-7.863) G51(-11.571,-7.863) G53(-12.952,-7.863) G55(-14.079,-7.863) G57(-15.459,-7.863) H22(6.707,-6.734) H23(6.199,-7.14) H57(-15.743,-7.213) J22(6.707,-5.921) J23(6.199,-6.327) J58(-16.063,-6.487) K9(14.282,-5.453) K10(13.379,-5.614) K12(12.426,-5.614) K14(11.474,-5.614) K16(10.521,-5.614) K18(9.569,-5.614) K19(8.616,-5.614) K21(7.664,-5.614) K23(6.199,-5.514) K57(-15.743,-5.837) L10(13.838,-4.977) L11(12.902,-5.17) L13(11.95,-5.17) L15(10.997,-5.17) L17(10.045,-5.17) L18(9.092,-5.17) L20(8.135,-5.108) L22(6.707,-5.108) L58(-16.063,-5.186) M9(14.282,-4.5) M20(8.135,-4.295) M21(7.627,-4.702) M22(6.707,-4.295) M23(6.199,-4.702) M57(-15.743,-4.536) N10(13.838,-4.024) N21(7.627,-3.889) N23(6.199,-3.889) N58(-16.063,-3.886) P9(14.282,-3.548) P20(8.135,-3.482) P22(6.707,-3.482) P57(-15.743,-3.236) R10(13.838,-3.072) R20(8.135,-2.67) R21(7.627,-3.076) R22(6.707,-2.67) R23(6.199,-3.076) T9(14.282,-2.595) T21(7.627,-2.263) T23(6.199,-2.263) T58(-16.063,-2.585) U9(14.282,-1.643) U10(13.838,-2.119) U20(8.135,-1.857) U22(6.707,-1.857) U57(-15.743,-1.935) V10(13.838,-1.167) V21(7.627,-1.45) V23(6.199,-1.45) V58(-16.063,-1.285) W9(14.282,-0.69) W20(8.135,-1.044) W21(7.627,-0.638) W22(6.707,-1.044) W23(6.199,-0.638) W57(-15.743,-0.635) Y10(13.838,-0.214) Y20(8.135,-0.231) Y22(6.707,-0.231)
  round 0.305 smd: A8(14.776,-11.314) A9(13.862,-11.314) A11(12.948,-11.314) A12(12.198,-11.314) A14(11.284,-11.314) A15(10.37,-11.314) A17(9.62,-11.314) A18(8.706,-11.314) A20(7.791,-11.314) A21(7.042,-11.314) A23(6.128,-11.314) A24(5.291,-10.989) A25(4.6,-11.314) A27(3.474,-11.314) A28(2.783,-10.989) A29(2.093,-11.314) A31(0.966,-11.314) A32(0.276,-10.989) A33(-0.415,-11.314) A35(-1.541,-11.314) A36(-2.232,-10.989) A37(-2.922,-11.314) A39(-4.049,-11.314) A40(-4.739,-10.989) A41(-5.43,-11.314) A43(-6.556,-11.314) A44(-7.247,-10.989) A45(-7.937,-11.314) A47(-9.064,-11.314) A48(-9.754,-10.989) A49(-10.444,-11.314) A51(-11.571,-11.314) A52(-12.262,-10.989) A53(-12.952,-11.314) A55(-14.079,-11.314) A56(-14.769,-10.989) A57(-15.459,-11.314) AA1(19.314,0.402) AA2(18.664,0.402) AA3(18.014,0.364) AA4(17.363,0.364) AA59(-16.713,0.324) AA60(-17.363,0.324) AA61(-18.014,0.324) AA62(-18.664,0.362) AA63(-19.314,0.362) AB5(16.678,0.738) AB6(16.027,0.738) AB7(15.377,0.738) AB8(14.727,0.738) AC1(19.314,1.152) AC2(18.664,1.152) AC3(18.014,1.19) AC4(17.363,1.19) AC59(-16.713,1.15) AC60(-17.363,1.15) AC61(-18.014,1.15) AC62(-18.664,1.112) AC63(-19.314,1.112) AD1(19.314,1.901) AD2(18.664,1.901) AD3(18.014,1.863) AD4(17.363,1.863) AD5(16.678,1.691) AD6(16.027,1.691) AD7(15.377,1.691) AD8(14.727,1.691) AD59(-16.713,1.823) AD60(-17.363,1.823) AD61(-18.014,1.823) AD62(-18.664,1.861) AD63(-19.314,1.861) AE5(16.678,2.643) AE6(16.027,2.643) AE7(15.377,2.643) AE8(14.727,2.643) AE59(-16.713,2.648) AE60(-17.363,2.648) AE61(-18.014,2.648) AE62(-18.664,2.61) AE63(-19.314,2.61) AF1(19.314,2.65) AF2(18.664,2.65) AF3(18.014,2.688) AF4(17.363,2.688) AG1(19.314,3.4) AG2(18.664,3.4) AG3(18.014,3.361) AG4(17.363,3.361) AG5(16.678,3.596) AG6(16.027,3.596) AG7(15.377,3.596) AG8(14.727,3.596) AG21(7.359,3.807) AG60(-17.038,3.288) AG61(-17.689,3.288) AG62(-18.339,3.288) AG63(-18.989,3.288) AH1(19.314,4.149) AH2(18.664,4.149) AH3(18.014,4.187) AH4(17.363,4.187) AH10(13.662,4.162) AH11(12.849,4.162) AH13(12.036,4.162) AH14(11.223,4.162) AH16(10.41,4.162) AH17(9.598,4.162) AH19(8.785,4.162) AH20(7.972,4.162) AH60(-17.363,3.964) AH61(-18.014,3.964) AH62(-18.664,3.964) AH63(-19.314,3.964) AJ5(16.678,4.548) AJ6(16.027,4.548) AJ7(15.377,4.548) AJ8(14.727,4.548) AJ10(13.662,4.812) AJ11(12.849,4.812) AJ13(12.036,4.812) AJ14(11.223,4.812) AJ60(-17.038,4.64) AJ61(-17.689,4.64) AJ62(-18.339,4.64) AJ63(-18.989,4.64) AK1(19.314,4.898) AK2(18.664,4.898) AK3(18.014,4.86) AK4(17.363,4.86) AK8(15.011,5.137) AK18(9.466,4.952) AK20(8.513,4.952) AK21(7.561,4.952) AK60(-17.363,5.209) AK61(-18.014,5.209) AK62(-18.664,5.315) AK63(-19.314,5.315) AL1(19.314,5.647) AL2(18.664,5.647) AL3(18.014,5.686) AL4(17.363,5.686) AL5(16.413,5.462) AL7(15.575,5.462) AL8(15.011,5.787) AL10(13.657,5.462) AL11(13.093,5.787) AL13(11.738,5.462) AL15(11.174,5.787) AL17(10.092,5.268) AL18(9.466,5.602) AL20(8.513,5.602) AL21(7.561,5.602) AL22(6.608,5.602) AL23(5.786,5.602) AL25(4.81,5.602) AL26(3.858,5.602) AL28(2.905,5.602) AL29(1.953,5.602) AL31(1.054,5.277) AL32(0.49,5.602) AL33(-0.412,5.602) AL35(-1.415,5.602) AL36(-2.266,5.602) AL38(-3.32,5.602) AL39(-4.228,5.277) AL40(-4.817,5.602) AL42(-5.63,5.602) AL43(-6.582,5.602) AL45(-7.56,5.602) AL46(-8.487,5.602) AL48(-9.542,5.602) AL49(-10.443,5.602) AL51(-11.447,5.602) AL52(-12.269,5.602) AL54(-13.295,5.602) AL55(-14.248,5.602) AL57(-15.195,5.602) AL58(-16.094,5.602) AL60(-17.038,5.855) AL61(-17.689,5.855) AM1(19.314,6.397) AM2(18.664,6.397) AM3(18.014,6.359) AM4(17.363,6.359) AM5(16.413,6.112) AM7(15.575,6.112) AM8(15.011,6.437) AM10(13.657,6.112) AM11(13.093,6.437) AM13(11.738,6.112) AM15(11.174,6.437) AM17(10.092,5.919) AM18(9.466,6.252) AM20(8.513,6.252) AM21(7.561,6.252) AM22(6.608,6.252) AM23(5.786,6.252) AM25(4.81,6.252) AM26(3.858,6.252) AM28(2.905,6.252) AM29(1.953,6.252) AM31(1.054,5.927) AM32(0.49,6.252) AM33(-0.412,6.252) AM35(-1.415,6.252) AM36(-2.266,6.252) AM38(-3.32,6.252) AM40(-4.817,6.252) AM42(-5.63,6.252) AM43(-6.582,6.252) AM45(-7.56,6.252) AM46(-8.487,6.252) AM48(-9.542,6.252) AM49(-10.443,6.252) AM51(-11.447,6.252) AM52(-12.269,6.252) AM54(-13.295,6.252) AM55(-14.248,6.252) AM57(-15.195,6.252) AM58(-16.094,6.252) AM60(-17.363,6.501) AM61(-18.014,6.501) AM62(-18.664,6.395) AM63(-19.314,6.395) AN1(19.314,7.146) AN2(18.664,7.146) AN3(18.014,7.184) AN4(17.363,7.184) AN5(16.413,6.762) AN7(15.575,6.762) AN8(15.011,7.088) AN10(13.657,6.762) AN11(13.093,7.088) AN13(11.738,6.762) AN15(11.174,7.088) AN17(10.092,6.569) AN18(9.466,6.903) AN20(8.513,6.903) AN21(7.561,6.903) AN22(6.608,6.903) AN23(5.786,6.903) AN25(4.81,6.903) AN26(3.858,6.903) AN28(2.905,6.903) AN29(1.953,6.903) AN31(1.054,6.578) AN32(0.49,6.903) AN33(-0.412,6.903) AN35(-1.415,6.903) AN36(-2.266,6.903) AN38(-3.32,6.903) AN39(-4.228,6.578) AN40(-4.817,6.903) AN42(-5.63,6.903) AN43(-6.582,6.903) AN45(-7.56,6.903) AN46(-8.487,6.903) AN48(-9.542,6.903) AN49(-10.443,6.903) AN51(-11.447,6.903) AN52(-12.269,6.903) AN54(-13.295,6.903) AN55(-14.248,6.903) AN57(-15.195,6.903) AN58(-16.094,6.903) AN60(-17.038,7.07) AN61(-17.689,7.07) AN62(-18.339,7.07) AN63(-18.989,7.07) AP1(19.314,7.895) AP2(18.664,7.895) AP3(18.014,7.857) AP4(17.363,7.857) AP5(16.413,7.413) AP7(15.575,7.413) AP8(15.011,7.738) AP10(13.657,7.413) AP11(13.093,7.738) AP13(11.738,7.413) AP15(11.174,7.738) AP17(10.092,7.219) AP18(9.466,7.553) AP20(8.513,7.553) AP21(7.561,7.553) AP22(6.608,7.553) AP23(5.786,7.553) AP25(4.81,7.553) AP26(3.858,7.553) AP28(2.905,7.553) AP29(1.953,7.553) AP31(1.054,7.228) AP32(0.49,7.553) AP33(-0.412,7.553) AP35(-1.415,7.553) AP36(-2.266,7.553) AP38(-3.32,7.553) AP39(-4.228,7.228) AP40(-4.817,7.553) AP42(-5.63,7.553) AP43(-6.582,7.553) AP45(-7.56,7.553) AP46(-8.487,7.553) AP48(-9.542,7.553) AP49(-10.443,7.553) AP51(-11.447,7.553) AP52(-12.269,7.553) AP54(-13.295,7.553) AP55(-14.248,7.553) AP57(-15.195,7.553) AP58(-16.094,7.553) AP60(-17.363,7.746) AP61(-18.014,7.746) AP62(-18.664,7.746) AP63(-19.314,7.746) AR5(16.413,8.063) AR7(15.575,8.063) AR8(15.011,8.388) AR10(13.657,8.063) AR11(13.093,8.388) AR13(11.738,8.063) AR15(11.174,8.388) AR17(10.092,7.869) AR18(9.466,8.203) AR20(8.513,8.203) AR21(7.561,8.203) AR22(6.608,8.203) AR23(5.786,8.203) AR25(4.81,8.203) AR26(3.858,8.203) AR28(2.905,8.203) AR29(1.953,8.203) AR31(1.054,7.878) AR32(0.49,8.203) AR33(-0.412,8.203) AR35(-1.415,8.203) AR36(-2.266,8.203) AR38(-3.32,8.203) AR39(-4.228,7.878) AR40(-4.817,8.203) AR42(-5.63,8.203) AR43(-6.582,8.203) AR45(-7.56,8.203) AR46(-8.487,8.203) AR48(-9.542,8.203) AR49(-10.443,8.203) AR51(-11.447,8.203) AR52(-12.269,8.203) AR54(-13.295,8.203) AR55(-14.248,8.203) AR57(-15.195,8.203) AR58(-16.094,8.203) AT2(18.664,8.645) AT3(18.014,8.683) AT4(17.363,8.683) AT5(16.413,8.713) AT7(15.575,8.713) AT10(13.657,8.713) AT13(11.738,8.713) AT35(-1.122,8.905) AT37(-2.697,8.905) AT40(-4.272,8.905) AT42(-5.847,8.905) AT43(-7.422,8.905) AT46(-8.996,8.905) AT49(-10.597,8.933) AT61(-17.689,8.32) AT62(-18.498,8.376) AU2(18.659,9.333) AU3(17.999,9.333) AU4(17.338,9.333) AU6(15.977,9.363) AU7(15.151,9.363) AU8(14.478,9.363) AU10(13.653,9.363) AU11(12.98,9.363) AU12(12.154,9.363) AU14(11.481,9.363) AU15(10.656,9.363) AU16(10.092,9.038) AU17(9.454,9.363) AU18(8.778,9.038) AU19(8.21,9.363) AU20(7.563,9.038) AU21(6.917,9.363) AU22(6.348,9.038) AU23(5.672,9.363) AU24(4.996,9.038) AU25(4.321,9.363) AU26(3.645,9.038) AU27(3.076,9.363) AU28(2.43,9.038) AU29(1.783,9.363) AU30(1.214,9.038) AU31(0.539,9.363) AU33(-0.058,9.016) AU34(-0.66,9.363) AU35(-1.585,9.363) AU36(-2.235,9.363) AU37(-3.16,9.363) AU39(-3.81,9.363) AU40(-4.734,9.363) AU41(-5.385,9.363) AU42(-6.309,9.363) AU43(-6.959,9.363) AU44(-7.884,9.363) AU46(-8.534,9.363) AU47(-9.459,9.363) AU49(-10.109,9.363) AU50(-11.086,9.363) AU51(-11.666,9.038) AU52(-12.342,9.363) AU53(-13.017,9.038) AU54(-13.586,9.363) AU55(-14.233,9.038) AU56(-14.879,9.363) AU57(-15.448,9.038) AU58(-16.124,9.363) AU59(-16.688,9.038) AU60(-17.251,9.363) AU61(-17.963,9.087) AU62(-18.664,9.349) AV3(17.993,9.993) AV4(17.338,9.993) AV5(16.65,10.014) AV6(15.977,10.014) AV7(15.151,10.014) AV8(14.478,10.014) AV10(13.653,10.014) AV11(12.98,10.014) AV12(12.154,10.014) AV14(11.481,10.014) AV15(10.656,10.014) AV16(10.092,9.689) AV17(9.454,10.014) AV18(8.778,9.689) AV19(8.21,10.014) AV20(7.563,9.689) AV21(6.917,10.014) AV22(6.348,9.689) AV23(5.672,10.014) AV24(4.996,9.689) AV25(4.321,10.014) AV26(3.645,9.689) AV27(3.076,10.014) AV28(2.43,9.689) AV29(1.783,10.014) AV30(1.214,9.689) AV31(0.539,10.014) AV33(-0.086,9.689) AV34(-0.71,10.014) AV35(-1.535,10.014) AV36(-2.284,10.014) AV37(-3.11,10.014) AV39(-3.859,10.014) AV40(-4.685,10.014) AV41(-5.434,10.014) AV42(-6.26,10.014) AV43(-7.009,10.014) AV44(-7.834,10.014) AV46(-8.584,10.014) AV47(-9.409,10.014) AV49(-10.158,10.014) AV50(-10.984,10.014) AV51(-11.666,9.689) AV52(-12.342,10.014) AV53(-13.017,9.689) AV54(-13.586,10.014) AV55(-14.233,9.689) AV56(-14.879,10.014) AV57(-15.448,9.689) AV58(-16.124,10.014) AV59(-16.688,9.689) AV60(-17.251,10.014) AV61(-17.988,9.737) AW4(17.338,10.654) AW5(16.688,10.664) AW6(15.939,10.664) AW7(15.189,10.664) AW8(14.44,10.664) AW10(13.691,10.664) AW11(12.942,10.664) AW12(12.192,10.664) AW14(11.443,10.664) AW15(10.694,10.664) AW16(10.092,10.339) AW17(9.454,10.664) AW18(8.778,10.339) AW19(8.103,10.664) AW21(7.023,10.664) AW22(6.348,10.339) AW23(5.672,10.664) AW24(4.996,10.339) AW25(4.321,10.664) AW26(3.645,10.339) AW27(2.97,10.664) AW29(1.89,10.664) AW30(1.214,10.339) AW31(0.539,10.664) AW33(-0.137,10.339) AW34(-0.71,10.664) AW35(-1.535,10.664) AW36(-2.284,10.664) AW37(-3.11,10.664) AW39(-3.859,10.664) AW40(-4.685,10.664) AW41(-5.434,10.664) AW42(-6.26,10.664) AW43(-7.009,10.664) AW44(-7.834,10.664) AW46(-8.584,10.664) AW47(-9.409,10.664) AW49(-10.158,10.664) AW50(-10.984,10.664) AW51(-11.666,10.339) AW52(-12.342,10.664) AW53(-13.017,10.339) AW54(-13.693,10.664) AW56(-14.772,10.664) AW57(-15.448,10.339) AW58(-16.124,10.664) AW59(-16.688,10.339) AW60(-17.251,10.664) AY6(15.939,11.314) AY7(15.189,11.314) AY8(14.44,11.314) AY10(13.691,11.314) AY11(12.942,11.314) AY12(12.192,11.314) AY14(11.443,11.314) AY15(10.694,11.314) AY16(10.13,10.989) AY17(9.454,11.314) AY18(8.778,10.989) AY19(8.103,11.314) AY21(7.023,11.314) AY22(6.348,10.989) AY23(5.672,11.314) AY24(4.996,10.989) AY25(4.321,11.314) AY26(3.645,10.989) AY27(2.97,11.314) AY29(1.89,11.314) AY30(1.214,10.989) AY31(0.539,11.314) AY33(-0.137,10.989) AY34(-0.71,11.314) AY35(-1.535,11.314) AY36(-2.284,11.314) AY37(-3.11,11.314) AY39(-3.859,11.314) AY40(-4.685,11.314) AY41(-5.434,11.314) AY42(-6.26,11.314) AY43(-7.009,11.314) AY44(-7.834,11.314) AY46(-8.584,11.314) AY47(-9.409,11.314) AY49(-10.158,11.314) AY50(-10.984,11.314) AY51(-11.666,10.989) AY52(-12.342,11.314) AY53(-13.017,10.989) AY54(-13.693,11.314) AY56(-14.772,11.314) AY57(-15.448,10.989) AY58(-16.124,11.314) B4(17.393,-10.664) B5(16.176,-10.672) B6(15.196,-10.672) B8(14.423,-10.672) B9(13.598,-10.672) B11(12.617,-10.672) B12(11.845,-10.672) B14(11.02,-10.672) B15(10.039,-10.672) B17(9.267,-10.672) B18(8.442,-10.672) B20(7.461,-10.672) B21(7.042,-10.118) B22(6.689,-10.672) B23(5.864,-10.672) B24(5.291,-10.339) B25(4.6,-10.664) B26(4.037,-10.339) B27(3.474,-10.664) B28(2.783,-10.339) B29(2.093,-10.664) B30(1.53,-10.339) B31(0.966,-10.664) B32(0.276,-10.339) B33(-0.415,-10.664) B34(-0.978,-10.339) B35(-1.541,-10.664) B36(-2.232,-10.339) B37(-2.922,-10.664) B38(-3.485,-10.339) B39(-4.049,-10.664) B40(-4.739,-10.339) B41(-5.43,-10.664) B42(-5.993,-10.339) B43(-6.556,-10.664) B44(-7.247,-10.339) B45(-7.937,-10.664) B46(-8.5,-10.339) B47(-9.064,-10.664) B48(-9.754,-10.339) B49(-10.444,-10.664) B50(-11.008,-10.339) B51(-11.571,-10.664) B52(-12.262,-10.339) B53(-12.952,-10.664) B54(-13.515,-10.339) B55(-14.079,-10.664) B56(-14.769,-10.339) B57(-15.459,-10.664) B58(-16.023,-10.339) B59(-16.586,-10.664) B60(-17.351,-10.654) C3(18.012,-10.012) C4(17.196,-10.042) C5(16.542,-10.118) C6(15.538,-10.118) C8(14.776,-10.118) C9(13.964,-10.118) C11(12.96,-10.118) C12(12.198,-10.118) C14(11.386,-10.118) C15(10.382,-10.118) C17(9.62,-10.118) C18(8.807,-10.118) C20(7.804,-10.118) C21(7.423,-9.529) C22(6.636,-9.529) C23(6.229,-10.118) C24(5.263,-9.282) C25(4.6,-10.014) C26(4.037,-9.689) C27(3.474,-10.014) C28(2.756,-9.282) C29(2.093,-10.014) C30(1.53,-9.689) C31(0.966,-10.014) C32(0.248,-9.282) C33(-0.415,-10.014) C34(-0.978,-9.689) C35(-1.541,-10.014) C36(-2.259,-9.282) C37(-2.922,-10.014) C38(-3.485,-9.689) C39(-4.049,-10.014) C40(-4.767,-9.282) C41(-5.43,-10.014) C42(-5.993,-9.689) C43(-6.556,-10.014) C44(-7.274,-9.282) C45(-7.937,-10.014) C46(-8.5,-9.689) C47(-9.064,-10.014) C48(-9.756,-9.282) C49(-10.444,-10.014) C50(-11.008,-9.689) C51(-11.571,-10.014) C52(-12.264,-9.323) C53(-12.952,-10.014) C54(-13.515,-9.689) C55(-14.079,-10.014) C56(-14.771,-9.323) C57(-15.459,-10.014) C58(-16.023,-9.689) C59(-16.586,-10.014) C61(-17.689,-10.077) D2(18.664,-9.24) D3(18.014,-9.278) D5(16.636,-9.472) D6(15.945,-9.529) D8(15.157,-9.529) D9(14.37,-9.529) D11(13.462,-9.529) D12(12.579,-9.529) D14(11.792,-9.529) D15(10.884,-9.529) D17(10.001,-9.529) D18(9.214,-9.529) D20(8.306,-9.529) D21(7.079,-8.891) D23(5.937,-9.529) D25(4.6,-9.363) D26(4.037,-9.038) D27(3.474,-9.363) D29(2.093,-9.363) D30(1.53,-9.038) D31(0.966,-9.363) D33(-0.415,-9.363) D34(-0.978,-9.038) D35(-1.541,-9.363) D37(-2.922,-9.363) D38(-3.485,-9.038) D39(-4.049,-9.363) D41(-5.43,-9.363) D42(-5.993,-9.038) D43(-6.556,-9.363) D45(-7.937,-9.363) D46(-8.5,-9.038) D47(-9.064,-9.363) D49(-10.444,-9.363) D50(-11.008,-9.038) D51(-11.571,-9.363) D53(-12.952,-9.363) D54(-13.515,-9.038) D55(-14.079,-9.363) D57(-15.459,-9.363) D58(-16.023,-9.038) D59(-16.586,-9.363) D60(-17.363,-9.513) D61(-18.014,-9.513) D62(-18.664,-9.28) E2(18.664,-8.589) E3(18.014,-8.627) E4(17.363,-8.627) E5(16.712,-8.695) E6(15.76,-8.695) E8(14.807,-8.695) E10(13.855,-8.695) E11(12.902,-8.695) E13(11.95,-8.695) E15(10.997,-8.695) E17(10.045,-8.695) E18(9.092,-8.695) E20(8.14,-8.695) E59(-16.713,-8.667) E60(-17.363,-8.667) E61(-18.014,-8.667) E62(-18.664,-8.629) F2(18.664,-7.84) F3(18.014,-7.802) F4(17.363,-7.802) F5(16.712,-8.045) F6(15.76,-8.045) F8(14.807,-8.045) F10(13.855,-8.045) F11(12.902,-8.045) F13(11.95,-8.045) F15(10.997,-8.045) F17(10.045,-8.045) F18(9.092,-8.045) F20(8.14,-8.045) F59(-16.713,-7.842) F60(-17.363,-7.842) F61(-18.014,-7.842) F62(-18.664,-7.88) F63(-19.314,-7.88) G1(19.314,-7.091) G2(18.664,-7.091) G3(18.014,-7.129) G4(17.363,-7.129) G5(16.712,-7.395) G6(15.76,-7.395) G8(14.807,-7.395) G10(13.855,-7.395) G11(12.902,-7.395) G13(11.95,-7.395) G15(10.997,-7.395) G17(10.045,-7.395) G18(9.092,-7.395) G20(8.14,-7.395) H5(16.712,-6.745) H6(15.76,-6.745) H8(14.807,-6.745) H10(13.855,-6.745) H11(12.902,-6.745) H13(11.95,-6.745) H15(10.997,-6.745) H17(10.045,-6.745) H18(9.092,-6.745) H20(8.14,-6.745) H59(-16.713,-7.169) H60(-17.363,-7.169) H61(-18.014,-7.169) H62(-18.664,-7.131) H63(-19.314,-7.131) J1(19.314,-6.341) J2(18.664,-6.341) J3(18.014,-6.303) J4(17.363,-6.303) J5(16.687,-6.094) J6(15.747,-6.094) J8(14.807,-6.094) J10(13.855,-6.094) J11(12.902,-6.094) J13(11.95,-6.094) J15(10.997,-6.094) J17(10.045,-6.094) J18(9.092,-6.094) J20(8.14,-6.094) J21(7.219,-6.328) J59(-16.713,-6.343) J60(-17.363,-6.343) J61(-18.014,-6.343) J62(-18.664,-6.381) J63(-19.314,-6.381) K1(19.314,-5.592) K2(18.664,-5.592) K3(18.014,-5.63) K4(17.363,-5.63) K59(-16.713,-5.67) K60(-17.363,-5.67) K61(-18.014,-5.67) K62(-18.664,-5.632) K63(-19.314,-5.632) L1(19.314,-4.843) L2(18.664,-4.843) L3(18.014,-4.805) L4(17.363,-4.805) L5(16.678,-4.977) L6(16.027,-4.977) L7(15.377,-4.977) L8(14.727,-4.977) L59(-16.713,-4.845) L60(-17.363,-4.845) L61(-18.014,-4.845) L62(-18.664,-4.883) L63(-19.314,-4.883) N1(19.314,-4.093) N2(18.664,-4.093) N3(18.014,-4.132) N4(17.363,-4.132) N5(16.678,-4.024) N6(16.027,-4.024) N7(15.377,-4.024) N8(14.727,-4.024) N59(-16.713,-4.172) N60(-17.363,-4.172) N61(-18.014,-4.172) N62(-18.664,-4.134) N63(-19.314,-4.134) P1(19.314,-3.344) P2(18.664,-3.344) P3(18.014,-3.306) P4(17.363,-3.306) P59(-16.713,-3.346) P60(-17.363,-3.346) P61(-18.014,-3.346) P62(-18.664,-3.384) P63(-19.314,-3.384) R5(16.678,-3.072) R6(16.027,-3.072) R7(15.377,-3.072) R8(14.727,-3.072) T1(19.314,-2.595) T2(18.664,-2.595) T3(18.014,-2.633) T4(17.363,-2.633) T59(-16.713,-2.673) T60(-17.363,-2.673) T61(-18.014,-2.673) T62(-18.664,-2.635) T63(-19.314,-2.635) U1(19.314,-1.846) U2(18.664,-1.846) U3(18.014,-1.807) U4(17.363,-1.807) U5(16.678,-2.119) U6(16.027,-2.119) U7(15.377,-2.119) U8(14.727,-2.119) U59(-16.713,-1.848) U60(-17.363,-1.848) U61(-18.014,-1.848) U62(-18.664,-1.886) U63(-19.314,-1.886) V1(19.314,-1.096) V2(18.664,-1.096) V3(18.014,-1.134) V4(17.363,-1.134) V5(16.678,-1.167) V6(16.027,-1.167) V7(15.377,-1.167) V8(14.727,-1.167) V59(-16.713,-1.174) V60(-17.363,-1.174) V61(-18.014,-1.174) V62(-18.664,-1.136) V63(-19.314,-1.136) Y1(19.314,-0.347) Y2(18.664,-0.347) Y3(18.014,-0.309) Y4(17.363,-0.309) Y5(16.678,-0.214) Y6(16.027,-0.214) Y7(15.377,-0.214) Y8(14.727,-0.214) Y59(-16.713,-0.349) Y60(-17.363,-0.349) Y61(-18.014,-0.349) Y62(-18.664,-0.387) Y63(-19.314,-0.387)
  round 0.33 smd: AK22(6.659,4.952) AK23(5.786,4.952) AK25(4.81,4.952) AK26(3.858,4.952) AK28(2.905,4.952) AK29(2.004,4.952) AK32(0.49,4.952) AK33(-0.412,4.952) AK35(-1.415,4.952) AK36(-2.266,4.952) AK38(-3.295,4.952) AK40(-4.792,4.952) AK42(-5.63,4.952) AK43(-6.582,4.952) AK45(-7.56,4.952) AK46(-8.462,4.952) AK48(-9.516,4.952) AK49(-10.418,4.952) AK51(-11.421,4.952) AK52(-12.269,4.952) AK54(-13.295,4.952) AK55(-14.248,4.952) AK57(-15.195,4.952) AK58(-16.094,4.952)
